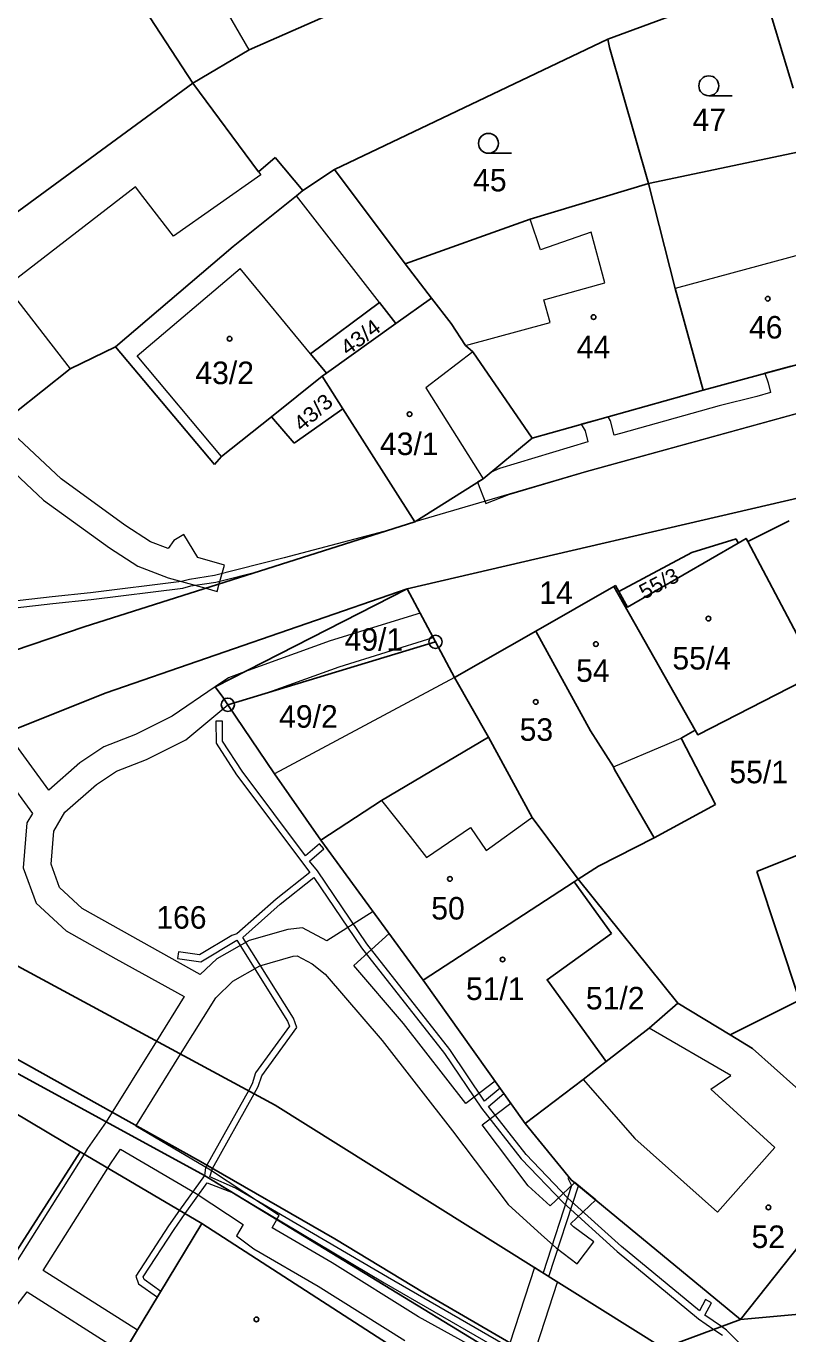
# Model space of a CAD drawing. Extents: x -606517 to -602431, y -1183120 to -1179397.
# Drawn here: x -605326.3 to -605268.8, y -1181010.4 to -1180911.8 of the extents above; entities that cross this region are included whole.
import ezdxf
from ezdxf.enums import TextEntityAlignment as Align

# ---------------------------------------------------------------- set-up
doc = ezdxf.new("R2010")
doc.units = 0
doc.header["$LTSCALE"] = 0.68
for name, color, linetype, lineweight in [('1', 7, 'Continuous', 25), ('13', 7, 'Continuous', 13), ('3', 7, 'Continuous', 25), ('4', 7, 'Continuous', 13), ('5', 7, 'Continuous', 25), ('8', 7, 'Continuous', 25)]:
    doc.layers.add(name, color=color, linetype=linetype, lineweight=lineweight)
doc.layers.add('2', color=7, linetype='Continuous')

msp = doc.modelspace()

# ---------------------------------------------------------------- linework, layer by layer
at = {"layer": '1'}
for p, q in [((-605309.42, -1180913.54), (-605259.99, -1180891.74)), ((-605282.37, -1180912.74), (-605270.8, -1180908.46)), ((-605268.38, -1180916.43), (-605270.8, -1180908.46)), ((-605317.33, -1180910.46), (-605313.69, -1180916.04)), ((-605302.99, -1180922.56), (-605282.37, -1180912.74)), ((-605282.24, -1180913.37), (-605282.37, -1180912.74)), ((-605279.3, -1180923.63), (-605282.24, -1180913.37)), ((-605313.69, -1180916.04), (-605308.73, -1180922.73)), ((-605266.97, -1180921.04), (-605279.3, -1180923.63)), ((-605308.73, -1180922.73), (-605307.46, -1180921.65)), ((-605307.46, -1180921.65), (-605305.38, -1180924.16)), ((-605305.38, -1180924.16), (-605302.99, -1180922.56)), ((-605297.66, -1180929.67), (-605302.99, -1180922.56)), ((-605305.87, -1180924.56), (-605305.38, -1180924.16)), ((-605279.3, -1180923.63), (-605288.22, -1180926.3)), ((-605277.29, -1180931.53), (-605279.3, -1180923.63)), ((-605288.22, -1180926.3), (-605297.66, -1180929.67)), ((-605295.67, -1180932.26), (-605297.66, -1180929.67)), ((-605275.18, -1180939.2), (-605277.29, -1180931.53)), ((-605299.59, -1180932.59), (-605304.8, -1180936.47)), ((-605298.36, -1180934.17), (-605295.67, -1180932.26)), ((-605294.19, -1180934.18), (-605295.67, -1180932.26)), ((-605293.1, -1180935.85), (-605294.19, -1180934.18)), ((-605319.52, -1180935.95), (-605322.95, -1180937.6)), ((-605312.04, -1180944.83), (-605319.52, -1180935.95)), ((-605292.56, -1180936.33), (-605293.1, -1180935.85)), ((-605262.57, -1180935.79), (-605275.18, -1180939.2)), ((-605303.6, -1180937.92), (-605304.8, -1180936.47)), ((-605288.08, -1180942.82), (-605292.56, -1180936.33)), ((-605322.95, -1180937.6), (-605327.11, -1180940.93)), ((-605303.6, -1180937.92), (-605303.92, -1180938.15)), ((-605303.92, -1180938.15), (-605307.75, -1180941.21)), ((-605302.36, -1180940.61), (-605303.92, -1180938.15)), ((-605275.18, -1180939.2), (-605288.08, -1180942.82)), ((-605302.36, -1180940.61), (-605306.03, -1180943.2)), ((-605296.94, -1180949.14), (-605302.36, -1180940.61)), ((-605307.75, -1180941.21), (-605311.53, -1180944.22)), ((-605306.03, -1180943.2), (-605307.75, -1180941.21)), ((-605288.08, -1180942.82), (-605291.77, -1180945.89)), ((-605311.53, -1180944.22), (-605312.04, -1180944.83)), ((-605291.77, -1180945.89), (-605296.94, -1180949.14)), ((-605297.51, -1180954.19), (-605262.69, -1180946.11)), ((-605296.94, -1180949.14), (-605321.89, -1180957.07)), ((-605271.8, -1180950.62), (-605268.68, -1180949.08)), ((-605276.02, -1180951.45), (-605272.69, -1180950.43)), ((-605272.69, -1180950.43), (-605272.53, -1180950.74)), ((-605281.54, -1180954.39), (-605276.02, -1180951.45)), ((-605320.22, -1180962.05), (-605297.51, -1180954.19)), ((-605297.51, -1180954.19), (-605312, -1180961.59)), ((-605295.37, -1180958.2), (-605297.51, -1180954.19)), ((-605281.92, -1180954.03), (-605287.79, -1180957.38)), ((-605275.77, -1180964.87), (-605281.92, -1180954.03)), ((-605321.89, -1180957.07), (-605343.44, -1180964.33)), ((-605293.93, -1180960.89), (-605287.79, -1180957.38)), ((-605287.79, -1180957.38), (-605283.67, -1180964.91)), ((-605311.04, -1180962.94), (-605295.37, -1180958.2)), ((-605293.93, -1180960.89), (-605295.37, -1180958.2)), ((-605312, -1180961.59), (-605311.42, -1180962.37)), ((-605291.38, -1180965.39), (-605293.93, -1180960.89)), ((-605346.03, -1180972.33), (-605320.22, -1180962.05)), ((-605311.42, -1180962.37), (-605311.04, -1180962.94)), ((-605311.04, -1180962.94), (-605307.52, -1180968.15)), ((-605291.38, -1180965.39), (-605299.45, -1180970.16)), ((-605288.08, -1180971.44), (-605291.38, -1180965.39)), ((-605283.67, -1180964.91), (-605281.94, -1180967.63)), ((-605276.84, -1180965.47), (-605275.77, -1180964.87)), ((-605274.24, -1180970.46), (-605276.84, -1180965.47)), ((-605281.94, -1180967.63), (-605281.87, -1180967.82)), ((-605307.52, -1180968.15), (-605304.02, -1180973.15)), ((-605281.87, -1180967.82), (-605278.88, -1180972.98)), ((-605299.45, -1180970.16), (-605304.02, -1180973.15)), ((-605278.88, -1180972.98), (-605274.24, -1180970.46)), ((-605284.6, -1180976.1), (-605288.08, -1180971.44)), ((-605261.72, -1180971.76), (-605271.13, -1180975.51)), ((-605304.02, -1180973.15), (-605296.29, -1180983.72)), ((-605283.07, -1180975.13), (-605278.88, -1180972.98)), ((-605284.6, -1180976.1), (-605283.07, -1180975.13)), ((-605271.13, -1180975.51), (-605267.89, -1180985.24)), ((-605284.6, -1180976.1), (-605284.9, -1180976.29)), ((-605277.07, -1180985.46), (-605284.6, -1180976.1)), ((-605352.34, -1180976.88), (-605312.8, -1180998.45)), ((-605333.38, -1180979.16), (-605307.47, -1180993.15)), ((-605296.29, -1180983.72), (-605288.59, -1180994.52)), ((-605313.11, -1180997.39), (-605335.61, -1180984.84)), ((-605277.07, -1180985.46), (-605279.24, -1180987.34)), ((-605273.13, -1180987.85), (-605277.07, -1180985.46)), ((-605267.89, -1180985.24), (-605273.13, -1180987.85)), ((-605322.19, -1180996.66), (-605337.91, -1180987.32)), ((-605282.48, -1180989.85), (-605279.24, -1180987.34)), ((-605271.45, -1180988.87), (-605273.13, -1180987.85)), ((-605266.37, -1180993.42), (-605271.45, -1180988.87)), ((-605282.48, -1180989.85), (-605284.22, -1180991.2)), ((-605284.22, -1180991.2), (-605288.59, -1180994.52)), ((-605307.47, -1180993.15), (-605278.18, -1181011.48)), ((-605288.59, -1180994.52), (-605285.12, -1180998.78)), ((-605329.72, -1181008.39), (-605322.19, -1180996.66)), ((-605322.19, -1180996.66), (-605313, -1181002.07)), ((-605313.11, -1180997.39), (-605302.96, -1181003.23)), ((-605272.35, -1181009.31), (-605262.85, -1180997.32)), ((-605289.7, -1181012.53), (-605312.8, -1180998.45)), ((-605285.12, -1180998.78), (-605272.35, -1181009.31)), ((-605326.09, -1181023.72), (-605313, -1181002.07)), ((-605313, -1181002.07), (-605298.57, -1181011.41)), ((-605302.96, -1181003.23), (-605296.19, -1181007.32)), ((-605272.35, -1181009.31), (-605244.71, -1181006.77)), ((-605282.12, -1181015.49), (-605296.19, -1181007.32)), ((-605278.18, -1181011.48), (-605272.35, -1181009.31))]:
    msp.add_line(p, q, dxfattribs=at)
for points in [[(-605328.34, -1180926.8), (-605313.69, -1180916.04), (-605309.42, -1180913.54)], [(-605319.52, -1180935.95), (-605310.63, -1180928.38), (-605305.87, -1180924.56)], [(-605303.6, -1180937.92), (-605298.36, -1180934.17), (-605299.59, -1180932.59)], [(-605281.54, -1180954.39), (-605280.88, -1180955.58), (-605272.53, -1180950.74)], [(-605271.8, -1180950.62), (-605268.11, -1180957.62), (-605267.68, -1180961.16), (-605275.58, -1180965.21), (-605275.77, -1180964.87)], [(-605272.53, -1180950.74), (-605271.93, -1180950.39), (-605271.8, -1180950.62)], [(-605281.92, -1180954.03), (-605281.79, -1180953.95), (-605281.54, -1180954.39)], [(-605282.09, -1180980.2), (-605284.9, -1180976.29), (-605296.29, -1180983.72)], [(-605282.48, -1180989.85), (-605286.95, -1180983.69), (-605282.09, -1180980.2)]]:
    msp.add_lwpolyline(points, dxfattribs=at)
at = {"layer": '13'}
for points in [[(-605268.55, -1180937.41), (-605270.52, -1180937.94), (-605270.27, -1180938.66), (-605270.09, -1180939.38), (-605271.12, -1180939.7), (-605273.95, -1180940.4), (-605281.4, -1180942.48), (-605281.89, -1180942.6), (-605282.16, -1180941.53), (-605282.34, -1180941.21), (-605284.37, -1180941.78), (-605284.08, -1180942.29), (-605283.87, -1180943.12), (-605290.53, -1180945.13), (-605291.18, -1180945.4), (-605291.77, -1180945.89), (-605292.2, -1180946.16), (-605291.56, -1180947.77), (-605289.83, -1180947.07), (-605283.98, -1180945.35), (-605265.27, -1180940.19)], [(-605333.69, -1180939.32), (-605324.94, -1180947.5), (-605319.98, -1180951.1), (-605317.82, -1180952.48), (-605315.54, -1180953.36), (-605312.71, -1180954.15), (-605311.69, -1180953.83), (-605311.29, -1180952.41), (-605313.3, -1180951.84), (-605314.35, -1180950.09), (-605315.11, -1180950.55), (-605315.55, -1180951.15), (-605316.88, -1180950.64), (-605318.82, -1180949.4), (-605323.62, -1180945.9), (-605331.31, -1180938.72)], [(-605329.31, -1180955.89), (-605324.24, -1180955.31), (-605321.35, -1180955.01), (-605314.44, -1180954.15), (-605313.83, -1180953.98), (-605311.94, -1180953.69), (-605308.54, -1180952.83), (-605299.28, -1180949.88), (-605306.78, -1180951.87), (-605312.04, -1180953.19), (-605313.93, -1180953.5), (-605314.54, -1180953.65), (-605321.41, -1180954.51), (-605324.3, -1180954.81), (-605329.37, -1180955.39)], [(-605329.67, -1180965.82), (-605325.79, -1180971.14), (-605326.2, -1180971.84), (-605326.48, -1180975.24), (-605325.51, -1180977.9), (-605323.25, -1180980), (-605319.5, -1180982.1), (-605314.33, -1180984.96), (-605316.42, -1180988.32), (-605314.6, -1180989.3), (-605311.95, -1180985.05), (-605310.66, -1180983.8), (-605308.62, -1180982.64), (-605306.1, -1180981.92), (-605305.81, -1180981.89), (-605304.68, -1180982.48), (-605303.69, -1180983.26), (-605299.39, -1180988.28), (-605294.09, -1180995.09), (-605289.89, -1181000.64), (-605287.36, -1181002.93), (-605286.27, -1181003.9), (-605284.67, -1181005.11), (-605283.43, -1181003.47), (-605284.95, -1181002.32), (-605285.19, -1181002.1), (-605283.28, -1181000.3), (-605284.86, -1180998.99), (-605286.71, -1181000.74), (-605288.37, -1180999.24), (-605291.84, -1180994.64), (-605289.68, -1180993), (-605290.86, -1180991.34), (-605293.09, -1180993.02), (-605297.79, -1180986.98), (-605301.54, -1180982.6), (-605298.86, -1180980.21), (-605300.07, -1180978.55), (-605303.56, -1180980.74), (-605305.41, -1180979.77), (-605306.5, -1180979.9), (-605309.42, -1180980.72), (-605311.88, -1180982.12), (-605313.12, -1180983.28), (-605322.03, -1180978.32), (-605323.75, -1180976.74), (-605324.38, -1180974.96), (-605324.18, -1180972.48), (-605323.33, -1180971.04), (-605320.95, -1180968.97), (-605319.44, -1180967.95), (-605317.18, -1180967.06), (-605314.21, -1180965.59), (-605311.04, -1180962.94), (-605308.3, -1180962.11), (-605302.65, -1180960.07), (-605295.54, -1180957.88), (-605296.53, -1180956.03), (-605303.31, -1180958.11), (-605309.79, -1180960.46), (-605311, -1180960.9), (-605312, -1180961.59), (-605315.25, -1180963.81), (-605318.02, -1180965.18), (-605320.4, -1180966.11), (-605322.21, -1180967.33), (-605324.56, -1180969.38), (-605327.71, -1180965.04)], [(-605269.81, -1181013.78), (-605273.4, -1181010.11), (-605273.78, -1181009.84), (-605275.04, -1181008.98), (-605274.55, -1181008.06), (-605274.99, -1181007.82), (-605275.45, -1181008.67), (-605281.33, -1181003.81), (-605285.37, -1181000.16), (-605288.52, -1180996.87), (-605291.36, -1180993.26), (-605290.2, -1180992.27), (-605290.49, -1180991.86), (-605291.66, -1180992.85), (-605294.28, -1180988.95), (-605300.56, -1180980.98), (-605304.28, -1180975.46), (-605304.87, -1180974.73), (-605303.79, -1180973.81), (-605304.11, -1180973.43), (-605305.18, -1180974.34), (-605309.96, -1180967.96), (-605311.43, -1180965.69), (-605311.45, -1180964.17), (-605311.95, -1180964.17), (-605311.93, -1180965.85), (-605310.38, -1180968.24), (-605304.86, -1180975.59), (-605307.4, -1180977.6), (-605310.37, -1180980.23), (-605310.73, -1180980.34), (-605313.18, -1180981.81), (-605314.76, -1180981.59), (-605314.83, -1180982.08), (-605313.08, -1180982.33), (-605310.37, -1180980.71), (-605306.54, -1180986.8), (-605306.39, -1180987.2), (-605308.94, -1180990.71), (-605309.21, -1180991.55), (-605309.49, -1180992.06), (-605309.05, -1180992.3), (-605308.75, -1180991.75), (-605308.48, -1180990.93), (-605305.83, -1180987.28), (-605306.08, -1180986.58), (-605309.92, -1180980.5), (-605307.08, -1180977.98), (-605304.54, -1180975.97), (-605300.96, -1180981.28), (-605294.68, -1180989.25), (-605291.91, -1180993.37), (-605288.9, -1180997.19), (-605285.71, -1181000.52), (-605281.65, -1181004.19), (-605275.52, -1181009.26), (-605274.36, -1181010.06), (-605273.72, -1181010.49)], [(-605284.82, -1181015.62), (-605296.65, -1181009.11), (-605303.16, -1181005.04), (-605307.69, -1181002.4), (-605307.34, -1181001.78), (-605312.8, -1180998.45), (-605320.21, -1180994.41), (-605321.62, -1180996.43)], [(-605327.27, -1181008.63), (-605326.18, -1181007.24), (-605318.91, -1181011.85), (-605317.86, -1181010.11), (-605324.98, -1181005.61), (-605320.1, -1180997.89), (-605319.9, -1180997.57), (-605319.13, -1180996.46), (-605313.44, -1180999.82), (-605309.89, -1181002.14), (-605310.38, -1181003.01), (-605309.07, -1181003.98), (-605304.22, -1181006.8), (-605297.69, -1181010.89)], [(-605321.62, -1180996.43), (-605321.88, -1180996.84), (-605327.07, -1181005.06)], [(-605287.55, -1181012.73), (-605298.98, -1181006.12), (-605310.47, -1180999.4), (-605312.4, -1180998.56), (-605312.19, -1180997.92), (-605312.62, -1180997.67), (-605312.73, -1180997.87), (-605312.8, -1180998.45), (-605314.68, -1181001.08), (-605315.51, -1181002.24), (-605317.99, -1181006.05), (-605317.78, -1181006.62), (-605316.36, -1181007.63), (-605316.1, -1181007.2), (-605317.36, -1181006.3), (-605317.43, -1181006.11), (-605315.09, -1181002.52), (-605314.25, -1181001.33), (-605312.61, -1180999.01), (-605310.65, -1180999.76), (-605299.24, -1181006.56), (-605288, -1181013.05)]]:
    msp.add_lwpolyline(points, dxfattribs=at)
for points in [[(-605312.71, -1180954.15), (-605311.85, -1180954.39), (-605311.69, -1180953.83)], [(-605316.42, -1180988.32), (-605320.21, -1180994.41), (-605312.8, -1180998.45), (-605307.34, -1181001.78), (-605307.17, -1181001.46), (-605312.36, -1180998.06), (-605317.99, -1180994.74), (-605314.6, -1180989.3)], [(-605309.05, -1180992.3), (-605309.49, -1180992.06), (-605312.62, -1180997.67), (-605312.19, -1180997.92)], [(-605285.38, -1180998.66), (-605285.1, -1180999.2), (-605287.25, -1181005.8), (-605286.81, -1181006.08), (-605284.58, -1180999.23), (-605285.12, -1180998.78), (-605285.26, -1180998.61)], [(-605290.14, -1181012.26), (-605289.7, -1181012.53), (-605288.38, -1181013.31), (-605286.16, -1181006.49), (-605287.9, -1181005.39)]]:
    msp.add_lwpolyline(points, close=True, dxfattribs=at)
at = {"layer": '3'}
for p, q in [((-605274.743, -1180917), (-605272.993, -1180917)), ((-605291.373, -1180921.34), (-605289.623, -1180921.34))]:
    msp.add_line(p, q, dxfattribs=at)
for centre in [(-605274.7429, -1180916.2498), (-605291.3729, -1180920.5898)]:
    msp.add_circle(centre, 0.75, dxfattribs=at)
at = {"layer": '4'}
for p, q in [((-605309.42, -1180913.54), (-605312.78, -1180907.77)), ((-605308.55, -1180922.97), (-605315.13, -1180927.6)), ((-605308.73, -1180922.73), (-605308.55, -1180922.97)), ((-605318.02, -1180923.86), (-605327.74, -1180931.4)), ((-605317.46, -1180924.59), (-605318.02, -1180923.86)), ((-605315.13, -1180927.6), (-605317.46, -1180924.59)), ((-605299.59, -1180932.59), (-605305.87, -1180924.56)), ((-605264.78, -1180928.16), (-605277.29, -1180931.53)), ((-605317.88, -1180936.62), (-605310.11, -1180930.03)), ((-605304.8, -1180936.47), (-605310.11, -1180930.03)), ((-605327.74, -1180931.4), (-605322.95, -1180937.6)), ((-605293.1, -1180935.85), (-605286.72, -1180934.11)), ((-605311.53, -1180944.22), (-605317.88, -1180936.62)), ((-605292.56, -1180936.33), (-605296.09, -1180939.04)), ((-605296.09, -1180939.04), (-605291.77, -1180945.89)), ((-605293.93, -1180960.89), (-605307.52, -1180968.15)), ((-605277.89, -1180965.91), (-605276.84, -1180965.47)), ((-605281.94, -1180967.63), (-605277.89, -1180965.91)), ((-605299.45, -1180970.16), (-605297.29, -1180972.89)), ((-605291.55, -1180973.93), (-605288.2, -1180971.53)), ((-605288.2, -1180971.53), (-605288.08, -1180971.44)), ((-605296.04, -1180974.47), (-605292.72, -1180972.2)), ((-605292.72, -1180972.2), (-605291.55, -1180973.93)), ((-605297.29, -1180972.89), (-605296.04, -1180974.47)), ((-605273.08, -1180990.9), (-605279.24, -1180987.34)), ((-605284.22, -1180991.2), (-605280.32, -1180995.67)), ((-605274.58, -1180991.95), (-605273.08, -1180990.9)), ((-605269.77, -1180996.34), (-605274.58, -1180991.95)), ((-605280.32, -1180995.67), (-605274.08, -1181001.21)), ((-605274.08, -1181001.21), (-605269.77, -1180996.34))]:
    msp.add_line(p, q, dxfattribs=at)
for points in [[(-605019.1, -1180918.73), (-605180.25, -1180932.22), (-605225.75, -1180935.39), (-605261.87, -1180939.25), (-605283.98, -1180945.35), (-605296.94, -1180949.14)], [(-605286.72, -1180934.11), (-605287.19, -1180932.39), (-605282.59, -1180931.12), (-605283.62, -1180927.3), (-605287.45, -1180928.62), (-605288.22, -1180926.3)]]:
    msp.add_lwpolyline(points, dxfattribs=at)
at = {"layer": '5'}
for centre in [(-605270.2968, -1180932.3092), (-605283.4368, -1180933.6992), (-605310.9068, -1180935.3292), (-605297.3268, -1180941.0192), (-605274.7768, -1180956.4392), (-605283.2668, -1180958.3692), (-605287.8068, -1180962.7292), (-605294.2768, -1180976.0792), (-605290.3068, -1180982.1592), (-605270.2468, -1181000.8592), (-605308.8868, -1181009.3092)]:
    msp.add_circle(centre, 0.175, dxfattribs=at)
at = {"layer": '8'}
for centre, radius in [((-605295.37, -1180958.1999), 0.5), ((-605295.37, -1180958.1999), 0.0303), ((-605311.04, -1180962.9399), 0.5), ((-605311.04, -1180962.9399), 0.0303)]:
    msp.add_circle(centre, radius, dxfattribs=at)

# ---------------------------------------------------------------- texts
at = {"layer": '2'}
for s, p in [('47', (-605275.97, -1180919.665)), ('45', (-605292.53, -1180924.215)), ('46', (-605271.71, -1180935.315)), ('44', (-605284.71, -1180936.805)), ('43/2', (-605313.49, -1180938.755)), ('43/1', (-605299.56, -1180944.105)), ('14', (-605287.54, -1180955.335)), ('49/1', (-605302.23, -1180958.865)), ('54', (-605284.76, -1180961.215)), ('49/2', (-605307.17, -1180964.675)), ('53', (-605289.02, -1180965.665)), ('50', (-605295.69, -1180979.145)), ('166', (-605316.44, -1180979.835)), ('52', (-605271.52, -1181003.925))]:
    msp.add_text(s, height=1.7, dxfattribs=at).set_placement(p)
for s, rotation, width, p in [('43/4', 37, 1.1, (-605300.6932, -1180935.6651)), ('43/3', 41, 1.1, (-605304.2326, -1180941.3093)), ('55/3', 28, 1.05, (-605278.2399, -1180954.2887))]:
    msp.add_text(s, height=1.139, rotation=rotation, dxfattribs=dict(at, width=width)).set_placement(p, align=Align.CENTER)
for s, p in [('55/4', (-605275.279, -1180960.285)), ('55/1', (-605270.979, -1180968.865)), ('51/1', (-605290.859, -1180985.215)), ('51/2', (-605281.809, -1180985.925))]:
    msp.add_text(s, height=1.7, dxfattribs=at).set_placement(p, align=Align.CENTER)

doc.saveas('drawing.dxf')
